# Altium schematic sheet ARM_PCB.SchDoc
size A3
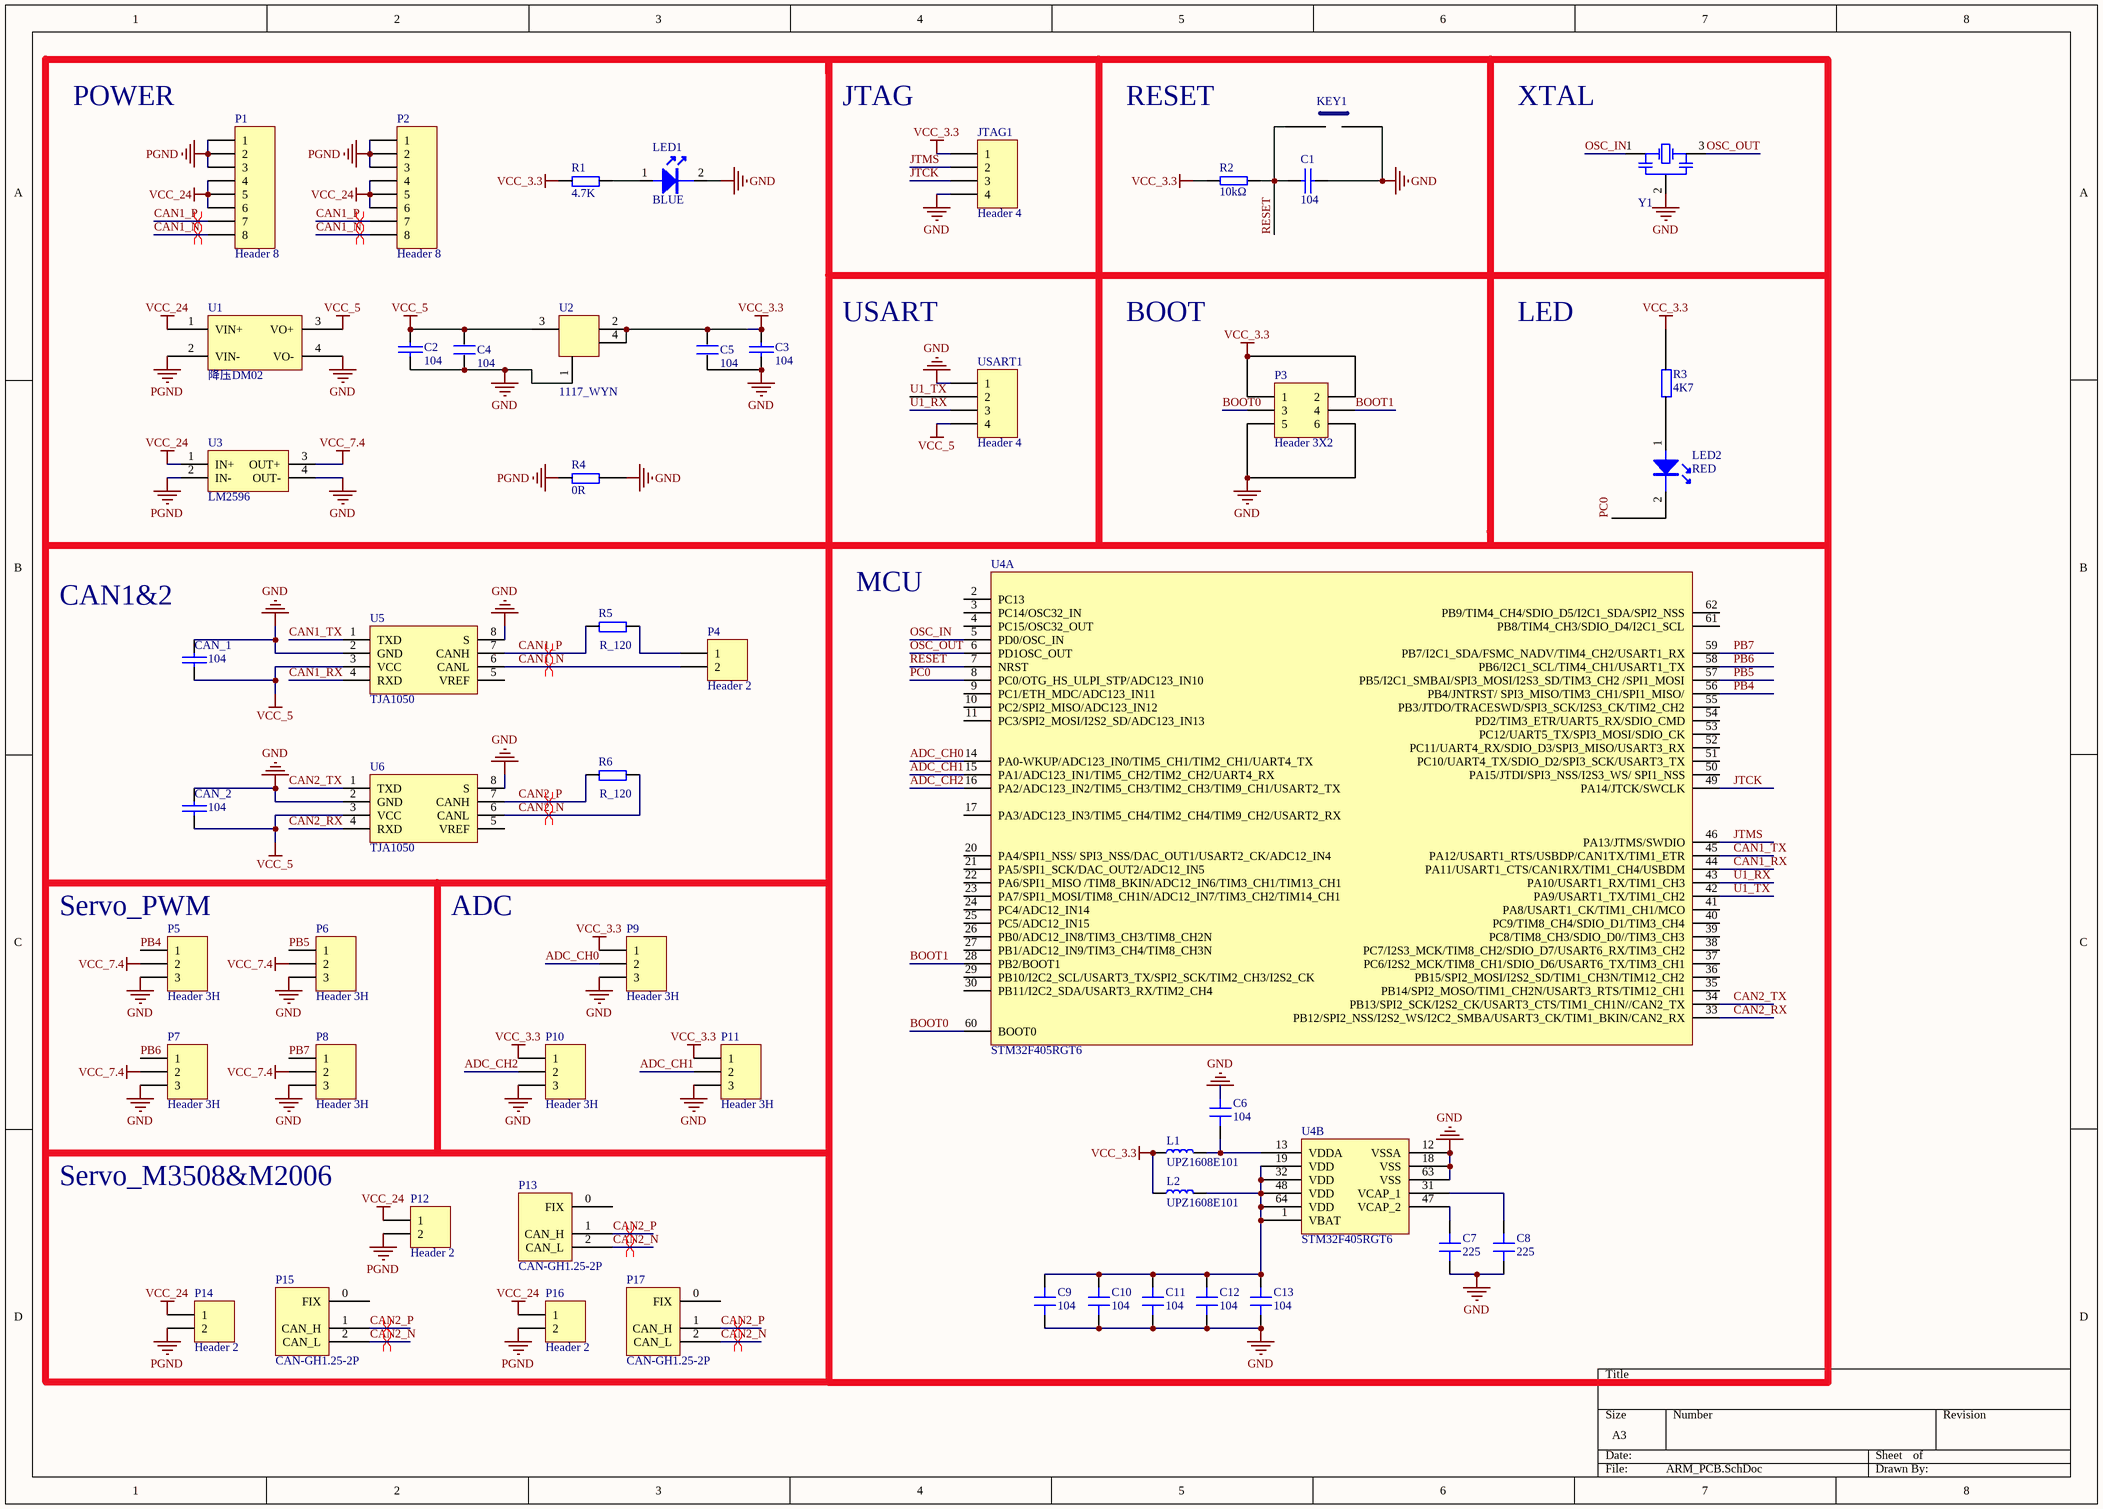
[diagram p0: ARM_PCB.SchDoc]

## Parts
C1  104  [C0603]
C2  104  [C0603]
C3  104  [C0603]
C4  104  [C0603]
C5  104  [C0603]
C6  104  [C0603/1608]
C7  225  [C0603/1608]
C8  225  [C0603/1608]
C9  104  [C0603/1608]
C10  104  [C0603/1608]
C11  104  [C0603/1608]
C12  104  [C0603/1608]
C13  104  [C0603/1608]
CAN_1  104  [C0603]
CAN_2  104  [C0603]
JTAG1  Header 4  [Header1*4_XH2.54_zhi]
KEY1  KEY2  [KEY_RESET]  (value not drawn)
L1  UPZ1608E101  [L0603/1608]
L2  UPZ1608E101  [L0603/1608]
LED1  Color: BLUE  [LED0603]  (hidden comment: LED BLUE)
LED2  Color: RED  [LED0603]  (hidden comment: LED RED)
P1  Header 8  [Header1*8_XH2.54_zhi]
P2  Header 8  [Header1*8_XH2.54_zhi]
P3  Header 3X2  [BOOT]
P4  Header 2  [TM]
P5  Header 3H  [Header1*3XH2.54]
P6  Header 3H  [Header1*3XH2.54]
P7  Header 3H  [Header1*3XH2.54]
P8  Header 3H  [Header1*3XH2.54]
P9  Header 3H  [Header1*3XH2.54]
P10  Header 3H  [Header1*3XH2.54]
P11  Header 3H  [Header1*3XH2.54]
P12  Header 2  [XT30_母]
P13  CAN-GH1.25-2P  [GH1.25-2P（立式）]
P14  Header 2  [XT30_母]
P15  CAN-GH1.25-2P  [GH1.25-2P（立式）]
P16  Header 2  [XT30_母]
P17  CAN-GH1.25-2P  [GH1.25-2P（立式）]
R1  4.7K  [R0603]
R2  10kΩ  [R0603]
R3  4K7  [R0603]
R4  0R  [R0603]
R5  R_120  [R0603]
R6  R_120  [R0603]
U1  降压DM02  [降压DM02]
U2  1117_WYN  [SOT-223]
U3  LM2596  [LM2596_big]
U4  STM32F405RGT6  [LQFP64]  (parts A,B of 2)
U5  TJA1050  [SO8_M]
U6  TJA1050  [SO8_M]
USART1  Header 4  [Header1*4_XH2.54_zhi]
Y1  Crystal_Cap  [XTAL-3213]  (value not drawn)

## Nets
GND: C1.2 C2.2 C3.2 C4.1 C5.1 C6.2 C7.1 C8.1 C9.1 C10.1 C11.1 C12.1 C13.1 CAN_1.1 CAN_2.1 JTAG1.4 KEY1.1 LED1.2(K) P3.5 P3.6 P5.3 P6.3 P7.3 P8.3 P9.3 P10.3 P11.3 R4.2 U1.4(VO-) U2.1 U3.4(OUT-) U4.12(VSSA) U4.18(VSS) U4.63(VSS) U5.2(GND) U5.8(S) U6.2(GND) U6.8(S) USART1.1 Y1.2(OSC2)
PGND: P1.1 P1.2 P1.3 P2.1 P2.2 P2.3 P12.2 P14.2 P16.2 R4.1 U1.2(VIN-) U3.2(IN-)
VCC_3.3: C3.1 C5.2 JTAG1.1 L1.1 L2.1 P3.1 P3.2 P9.1 P10.1 P11.1 R1.1 R2.2 R3.2 U2.2 U2.4
VCC_5: C2.1 C4.2 CAN_1.2 CAN_2.2 U1.3(VO+) U2.3 U5.3(VCC) U6.3(VCC) USART1.4
VCC_7.4: P5.2 P6.2 P7.2 P8.2 U3.3(OUT+)
VCC_24: P1.4 P1.5 P1.6 P2.4 P2.5 P2.6 P12.1 P14.1 P16.1 U1.1(VIN+) U3.1(IN+)
ADC_CH0: P9.2 U4.14(PA0-WKUP/ADC123_IN0/TIM5_CH1/TIM2_CH1/UART4_TX)
ADC_CH1: P11.2 U4.15(PA1/ADC123_IN1/TIM5_CH2/TIM2_CH2/UART4_RX)
ADC_CH2: P10.2 U4.16(PA2/ADC123_IN2/TIM5_CH3/TIM2_CH3/TIM9_CH1/USART2_TX)
BOOT0: P3.3 U4.60(BOOT0)
BOOT1: P3.4 U4.28(PB2/BOOT1)
CAN1_N: P1.8 P2.8 P4.2 U5.6(CANL)
CAN1_P: P1.7 P2.7 R5.1 U5.7(CANH)
CAN1_RX: U4.44(PA11/USART1_CTS/CAN1RX/TIM1_CH4/USBDM) U5.4(RXD)
CAN1_TX: U4.45(PA12/USART1_RTS/USBDP/CAN1TX/TIM1_ETR) U5.1(TXD)
CAN2_N: P13.2(CAN_L) P15.2(CAN_L) P17.2(CAN_L) R6.2 U6.6(CANL)
CAN2_P: P13.1(CAN_H) P15.1(CAN_H) P17.1(CAN_H) R6.1 U6.7(CANH)
CAN2_RX: U4.33(PB12/SPI2_NSS/I2S2_WS/I2C2_SMBA/USART3_CK/TIM1_BKIN/CAN2_RX) U6.4(RXD)
CAN2_TX: U4.34(PB13/SPI2_SCK/I2S2_CK/USART3_CTS/TIM1_CH1N//CAN2_TX) U6.1(TXD)
JTCK: JTAG1.3 U4.49(PA14/JTCK/SWCLK)
JTMS: JTAG1.2 U4.46(PA13/JTMS/SWDIO)
OSC_IN: U4.5(PD0/OSC_IN) Y1.1(OSC1)
OSC_OUT: U4.6(PD1OSC_OUT) Y1.3(OSC3)
PB4: P5.1 U4.56(PB4/JNTRST/_SPI3_MISO/TIM3_CH1/SPI1_MISO/)
PB5: P6.1 U4.57(PB5/I2C1_SMBAI/SPI3_MOSI/I2S3_SD/TIM3_CH2_/SPI1_MOSI)
PB6: P7.1 U4.58(PB6/I2C1_SCL/TIM4_CH1/USART1_TX)
PB7: P8.1 U4.59(PB7/I2C1_SDA/FSMC_NADV/TIM4_CH2/USART1_RX)
PC0: LED2.2(K) U4.8(PC0/OTG_HS_ULPI_STP/ADC123_IN10)
RESET: C1.1 KEY1.2 R2.1 U4.7(NRST)
U1_RX: U4.43(PA10/USART1_RX/TIM1_CH3) USART1.3
U1_TX: U4.42(PA9/USART1_TX/TIM1_CH2) USART1.2
NetC6_1: C6.1 L1.2 U4.13(VDDA)
NetC7_2: C7.2 U4.47(VCAP_2)
NetC8_2: C8.2 U4.31(VCAP_1)
NetC9_2: C9.2 C10.2 C11.2 C12.2 C13.2 L2.2 U4.1(VBAT) U4.19(VDD) U4.32(VDD) U4.48(VDD) U4.64(VDD)
NetLED1_1: LED1.1(A) R1.2
NetLED2_1: LED2.1(A) R3.1
NetP4_1: P4.1 R5.2

Not connected (* = marked no-connect by the designer): P13 0(FIX); P15 0(FIX); P17 0(FIX); U4 2(PC13) 3(PC14/OSC32_IN) 4(PC15/OSC32_OUT) 9(PC1/ETH_MDC/ADC123_IN11) 10(PC2/SPI2_MISO/ADC123_IN12) 11(PC3/SPI2_MOSI/I2S2_SD/ADC123_IN13) 17(PA3/ADC123_IN3/TIM5_CH4/TIM2_CH4/TIM9_CH2/USART2_RX) 20(PA4/SPI1_NSS/_SPI3_NSS/DAC_OUT1/USART2_CK/ADC12_IN4) 21(PA5/SPI1_SCK/DAC_OUT2/ADC12_IN5) 22(PA6/SPI1_MISO_/TIM8_BKIN/ADC12_IN6/TIM3_CH1/TIM13_CH1) 23(PA7/SPI1_MOSI/TIM8_CH1N/ADC12_IN7/TIM3_CH2/TIM14_CH1) 24(PC4/ADC12_IN14) 25(PC5/ADC12_IN15) 26(PB0/ADC12_IN8/TIM3_CH3/TIM8_CH2N) 27(PB1/ADC12_IN9/TIM3_CH4/TIM8_CH3N) 29(PB10/I2C2_SCL/USART3_TX/SPI2_SCK/TIM2_CH3/I2S2_CK) 30(PB11/I2C2_SDA/USART3_RX/TIM2_CH4) 35(PB14/SPI2_MOSO/TIM1_CH2N/USART3_RTS/TIM12_CH1) 36(PB15/SPI2_MOSI/I2S2_SD/TIM1_CH3N/TIM12_CH2) 37(PC6/I2S2_MCK/TIM8_CH1/SDIO_D6/USART6_TX/TIM3_CH1) 38(PC7/I2S3_MCK/TIM8_CH2/SDIO_D7/USART6_RX/TIM3_CH2) 39(PC8/TIM8_CH3/SDIO_D0//TIM3_CH3) 40(PC9/TIM8_CH4/SDIO_D1/TIM3_CH4) 41(PA8/USART1_CK/TIM1_CH1/MCO) 50(PA15/JTDI/SPI3_NSS/I2S3_WS/_SPI1_NSS) 51(PC10/UART4_TX/SDIO_D2/SPI3_SCK/USART3_TX) 52(PC11/UART4_RX/SDIO_D3/SPI3_MISO/USART3_RX) 53(PC12/UART5_TX/SPI3_MOSI/SDIO_CK) 54(PD2/TIM3_ETR/UART5_RX/SDIO_CMD) 55(PB3/JTDO/TRACESWD/SPI3_SCK/I2S3_CK/TIM2_CH2) 61(PB8/TIM4_CH3/SDIO_D4/I2C1_SCL) 62(PB9/TIM4_CH4/SDIO_D5/I2C1_SDA/SPI2_NSS); U5 5(VREF); U6 5(VREF)

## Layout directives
differential pair: CAN1_N, CAN1_P, CAN2_N, CAN2_P

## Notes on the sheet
- POWER
- JTAG
- RESET
- XTAL
- USART
- BOOT
- LED
- CAN1&2
- MCU
- (near P5) Servo_PWM
- ADC
- Servo_M3508&M2006

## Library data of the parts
C1-C3 CAN_1 CAN_2 = CAP_WYN
C4 C5 = Cap
C6-C13 = 陶瓷电容
JTAG1 USART1 = Header 4: Header, 4-Pin
KEY1 = KEY
L1 L2 = 磁珠: 贴片磁珠
LED1 LED2 = LED
P1 P2 = Header 8: Header, 8-Pin
P3 = Header 3X2: Header, 3-Pin, Dual row
P13 P15 P17 = CAN-GH1.25-2P: CAN-GH1.25-2P端子座
R1 R5 R6 = R
R2 = RES_WYN
R3 R4 = Resistor
U3 = DC-DC稳压模块: 云辉 LM2596S DC-DC降压电源模块
U4 = STM32F405RGT6: 微控制器STM32F405RGT6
